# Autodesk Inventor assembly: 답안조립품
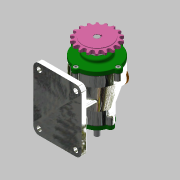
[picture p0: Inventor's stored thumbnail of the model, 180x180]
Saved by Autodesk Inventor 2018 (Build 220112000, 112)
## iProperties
Created: 2020-12
Part Number: 답안조립품
Material: 일반
Document SubType Name: Assembly
Designer: home
Author: home
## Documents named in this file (15)
- C:\Users\home\Desktop\701206V1021\답안조립품.iam
- C:\Users\home\Desktop\701206V1021\본체.ipt
- C:\Users\home\Desktop\701206V1021\앞커버.ipt
- C:\Users\home\Desktop\701206V1021\뒤커버.ipt
- C:\Users\home\Desktop\701206V1021\개스킷 A.ipt
- C:\Users\home\Desktop\701206V1021\개스킷 B.ipt
- C:\Users\home\Desktop\701206V1021\베어링 6200.ipt
- C:\Users\home\Desktop\701206V1021\베어링 6203.ipt
- C:\Users\home\Desktop\701206V1021\축.ipt
- C:\Users\home\Desktop\701206V1021\오일 실 10 20 7.ipt
- C:\Users\home\Desktop\701206V1021\오일 실 17 30 8.ipt
- C:\Users\home\Desktop\701206V1021\스프로킷.ipt
- C:\Users\home\Desktop\701206V1021\키 4x4x14.ipt
- C:\Users\home\Desktop\701206V1021\볼트 M5.ipt
- C:\Users\home\Desktop\701206V1021\마개.ipt
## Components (2 placed, 2 different names)
1. 개스킷 A:1
2. 개스킷 B:1
